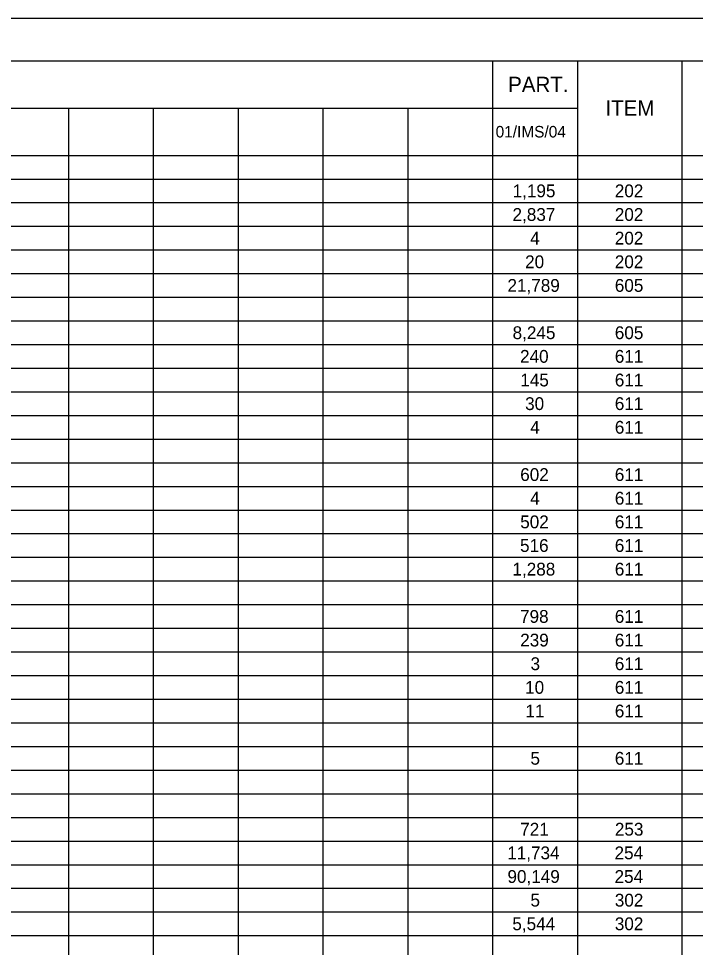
# Model space of a CAD drawing. Extents: x 0 to 34, y 0 to 22.
# Drawn here: x 8.95 to 16.96, y 11 to 22 of the extents above; entities that cross this region are included whole.
import ezdxf

# ---------------------------------------------------------------- set-up
doc = ezdxf.new("R2010")
doc.units = 0
for name, color, linetype in [('Default', 7, 'Continuous'), ('SH_Border', 7, 'Continuous'), ('SH_Cut_Line', 7, 'Continuous')]:
    doc.layers.add(name, color=color, linetype=linetype)

msp = doc.modelspace()

# ---------------------------------------------------------------- linework, layer by layer
at = {"layer": 'Default'}
for p, q in [((1.5, 21.5), (32, 21.5)), ((14.56, 21.5), (14.56, 0.5)), ((15.564, 21.5), (15.564, 0.5)), ((16.799, 21.5), (16.799, 0.5)), ((1.5, 20.94), (15.564, 20.94)), ((9.537, 20.94), (9.537, 0.5)), ((10.541, 20.94), (10.541, 0.5)), ((11.546, 20.94), (11.546, 0.5)), ((12.55, 20.94), (12.55, 0.5)), ((13.555, 20.94), (13.555, 0.5)), ((1.5, 20.38), (32, 20.38)), ((1.5, 20.1), (32, 20.1)), ((1.5, 19.82), (32, 19.82)), ((1.5, 19.54), (32, 19.54)), ((1.5, 19.26), (32, 19.26)), ((1.5, 18.98), (32, 18.98)), ((1.5, 18.7), (32, 18.7)), ((1.5, 18.42), (32, 18.42)), ((1.5, 18.14), (32, 18.14)), ((1.5, 17.86), (32, 17.86)), ((1.5, 17.58), (32, 17.58)), ((1.5, 17.3), (32, 17.3)), ((1.5, 17.02), (32, 17.02)), ((1.5, 16.74), (32, 16.74)), ((1.5, 16.46), (32, 16.46)), ((1.5, 16.18), (32, 16.18)), ((1.5, 15.9), (32, 15.9)), ((1.5, 15.62), (32, 15.62)), ((1.5, 15.34), (32, 15.34)), ((1.5, 15.06), (32, 15.06)), ((1.5, 14.78), (32, 14.78)), ((1.5, 14.5), (32, 14.5)), ((1.5, 14.22), (32, 14.22)), ((1.5, 13.94), (32, 13.94)), ((1.5, 13.66), (32, 13.66)), ((1.5, 13.38), (32, 13.38)), ((1.5, 13.1), (32, 13.1)), ((1.5, 12.82), (32, 12.82)), ((1.5, 12.54), (32, 12.54)), ((1.5, 12.26), (32, 12.26)), ((1.5, 11.98), (32, 11.98)), ((1.5, 11.7), (32, 11.7)), ((1.5, 11.42), (32, 11.42)), ((1.5, 11.14), (32, 11.14))]:
    msp.add_line(p, q, dxfattribs=at)
at = {"layer": 'SH_Border'}
msp.add_lwpolyline([(1.5, 21.5), (33.5, 21.5), (33.5, 0.5), (1.5, 0.5)], close=True, dxfattribs=at)
at = {"layer": 'SH_Cut_Line'}
msp.add_lwpolyline([(0, 0), (34, 0), (34, 22), (0, 22)], close=True, dxfattribs=at)

# ---------------------------------------------------------------- texts
at = {"layer": 'Default'}
for s, height, p in [('PART.', 0.1818, (14.744, 21.129)), ('ITEM', 0.1818, (15.896, 20.849)), ('01/IMS/04', 0.1364, (14.596, 20.592)), ('1,195', 0.1515, (14.797, 19.884)), ('202', 0.1515, (16.007, 19.884)), ('2,837', 0.1515, (14.796, 19.604)), ('202', 0.1515, (16.007, 19.604)), ('4', 0.152, (15.005, 19.324)), ('202', 0.1515, (16.007, 19.324)), ('20', 0.1515, (14.945, 19.044)), ('202', 0.1515, (16.007, 19.044)), ('21,789', 0.1515, (14.736, 18.764)), ('605', 0.1515, (16.007, 18.764)), ('8,245', 0.1515, (14.797, 18.204)), ('605', 0.1515, (16.007, 18.204)), ('240', 0.1515, (14.885, 17.924)), ('611', 0.1515, (16.007, 17.924)), ('145', 0.1515, (14.888, 17.644)), ('611', 0.1515, (16.007, 17.644)), ('30', 0.1515, (14.945, 17.364)), ('611', 0.1515, (16.007, 17.364)), ('4', 0.152, (15.005, 17.084)), ('611', 0.1515, (16.007, 17.084)), ('602', 0.1515, (14.887, 16.524)), ('611', 0.1515, (16.007, 16.524)), ('4', 0.152, (15.005, 16.244)), ('611', 0.1515, (16.007, 16.244)), ('502', 0.1515, (14.887, 15.964)), ('611', 0.1515, (16.007, 15.964)), ('516', 0.1515, (14.885, 15.684)), ('611', 0.1515, (16.007, 15.684)), ('1,288', 0.1515, (14.795, 15.404)), ('611', 0.1515, (16.007, 15.404)), ('798', 0.1515, (14.885, 14.844)), ('611', 0.1515, (16.007, 14.844)), ('239', 0.1515, (14.887, 14.564)), ('611', 0.1515, (16.007, 14.564)), ('3', 0.152, (15.009, 14.284)), ('611', 0.1515, (16.007, 14.284)), ('10', 0.1515, (14.945, 14.004)), ('611', 0.1515, (16.007, 14.004)), ('11', 0.1515, (14.948, 13.724)), ('611', 0.1515, (16.007, 13.724)), ('5', 0.152, (15.008, 13.164)), ('611', 0.1515, (16.007, 13.164)), ('721', 0.1515, (14.887, 12.324)), ('253', 0.1515, (16.008, 12.324)), ('11,734', 0.1515, (14.733, 12.044)), ('254', 0.1515, (16.004, 12.044)), ('90,149', 0.1515, (14.736, 11.764)), ('254', 0.1515, (16.004, 11.764)), ('5', 0.152, (15.008, 11.484)), ('302', 0.1515, (16.007, 11.484)), ('5,544', 0.1515, (14.794, 11.204)), ('302', 0.1515, (16.007, 11.204))]:
    msp.add_text(s, height=height, dxfattribs=at).set_placement(p)

doc.saveas('drawing.dxf')
